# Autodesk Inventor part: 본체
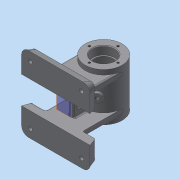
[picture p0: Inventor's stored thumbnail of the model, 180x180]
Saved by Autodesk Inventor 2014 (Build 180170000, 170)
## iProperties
Created: 2016-07
Part Number: 본체
Material: 일반
Document SubType Name: Modeling
Designer: 406-9
Density: 1 g/cm^3
Appearance: 기본값
Author: 406-9
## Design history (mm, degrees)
sketch "스케치1"
  geometry: L1 (-40, 55)-(40, 55); L2 (50, 45)-(50, -45); L3 (40, -55)-(-40, -55); L4 (-50, -45)-(-50, 45); L5 (-50, 55)-(50, -55); L6 (50, 55)-(-50, -55); A1 r 10 centre (-40, 45) between (-40, 55) and (-50, 45); A2 r 10 centre (40, 45) between (50, 45) and (40, 55); A3 r 10 centre (40, -45) between (40, -55) and (50, -45); A4 r 10 centre (-40, -45) between (-50, -45) and (-40, -55); 1 further point
  constraints: 12 end point, 8 point on circle, 8 point on line, 8 tangent, 4 centre point, 3 equal radius, 2 midpoint, 2 parallel, 1 horizontal, 1 perpendicular
  dimensions: "d0" = 100 distance of L5.end L6.end; "d1" = 110 distance of L6.end L5.start; "d119" = 10 radius of A1
sketch "스케치3"
  geometry: C1 r 27 at (0, 70); 1 further point
  constraints: 1 centre point, 1 vertical alignment
  dimensions: "d5" = 54 diameter of C1; "d6" = 70 distance of point (0, 0) C1.centre
extrude "돌출2" join sketch "스케치3" stored distance "d7" = 70; taper "d8" = 0 deg
node "작업 평면2"
sketch "스케치5"
  geometry: L1 (27, 35)-(-27, 35) reference; L2 (-27, -35)-(27, -35) reference; L3 (0, 35)-(0, -35); L4 (0, 35)-(-16, 35); L5 (-16, 35)-(-16, 23.3); L6 (-15.7, 23)-(-14, 23); L7 (-14, 23)-(-14, 21); L8 (-14, 21)-(-19, 21); L9 (-22, 18)-(-22, -18); L10 (-19, -21)-(-14, -21); L11 (-14, -21)-(-14, -23); L12 (-14, -23)-(-15.7, -23); L13 (-16, -23.3)-(-16, -35); L14 (0, -35)-(-16, -35); A1 r 3 centre (-19, -18) between (-22, -18) and (-19, -21); A2 r 3 centre (-19, 18) between (-19, 21) and (-22, 18); A3 r 0.3 centre (-15.7, -23.3) between (-15.7, -23) and (-16, -23.3); A4 r 0.3 centre (-15.7, 23.3) between (-16, 23.3) and (-15.7, 23); 5 further points
  constraints: 24 end point, 9 point on line, 8 point on circle, 8 tangent, 5 perpendicular, 4 centre point, 4 parallel, 2 collinear, 2 equal radius, 2 midpoint, 1 horizontal, 1 vertical
  dimensions: "d19" = 32 diameter of L5 L3; "d20" = 28 diameter of L7 L3; "d21" = 44 diameter of L9 L3; "d22" = 42 distance of point (-22, 21) point (-22, -21); "d23" = 12 distance of L4.end point (-16, 23); "d24" = 12 distance of point (-16, -23) L13.end; "d25" = 2 distance of L10.end L11.end; "d27" = 3 radius of A1; "d28" = 0.3 radius of A3
revolve "회전1" sketch "스케치5" stored, may be unused: angle "d26" = 90 deg
sketch "스케치6" dims "d29" = 42
  geometry: C1 r 16 at (0, 0) reference; 3 further points
  constraints: 2 vertical alignment, 1 coincident, 2 other
hole "구멍1" sketch "스케치6" at (0, 21) diameter "d30" = 3.242; stored, may be unused: countersink angle "d34" = 90 deg, drill point angle "d36" = 118 deg; dims "d31" = 8, "d32" = 4, "d33" = 2, "d35" = 10
sketch "스케치7"
  geometry: L1 (-27, 70)-(27, 70); L2 (0, 70)-(15.898, 44.559); L3 (0, 97)-(0, 43); L4 (15.898, 44.559)-(20.986, 47.738); L5 (20.986, 47.738)-(17.806, 52.826); L6 (17.806, 52.826)-(12.718, 49.647); A1 r 27 centre (0, 70) between (-27, 70) and (27, 70) reference; 1 further point
  constraints: 12 end point, 4 perpendicular, 4 point on circle, 2 midpoint, 1 coincident, 1 horizontal, 1 point on line
  dimensions: "d40" = 30 distance of L2.start L2.end; "d41" = 32 deg angle of L3 L2; "d42" = 12 diameter of L5 L2; "d43" = 6 distance of L4.end L5.end
node "작업 평면5"
sketch "스케치10"
  geometry: L1 (45, -20)-(22, -20); L2 (22, -20)-(22, 20); L3 (22, 20)-(45, 20); L4 (32, -8)-(32, 8); L5 (35.5, -8)-(35.5, 8); L6 (28.5, 8)-(28.5, -8); L7 (45, -20)-(45, 20); L8 (43, -35)-(43, 35) reference; A1 r 3.5 centre (32, -8) between (28.5, -8) and (35.5, -8); A2 r 3.5 centre (32, 8) between (35.5, 8) and (28.5, 8); 2 further points
  constraints: 16 end point, 4 point on circle, 4 tangent, 3 parallel, 2 centre point, 1 horizontal, 1 horizontal alignment, 1 midpoint, 1 perpendicular
  dimensions: "d62" = 32 distance of point (0, 0) point (32, 0); "d64" = 3.5 radius of A2; "d65" = 23 dimension on A2 A1; "d159" = 23 distance of L2.end L3.end; "d160" = 2 distance between parallel lines of L7 L8; "d161" = 20 distance from line of point (0, 0) L3; "d162" = 20 distance from line of L1 point (32, 0)
node "작업 평면3"
sketch "스케치11"
  geometry: C1 r 5 at (0, 0); 1 further point
  constraints: 1 centre point, 1 coincident
  dimensions: "d69" = 10 diameter of C1
extrude "돌출6" join sketch "스케치11" stored distance "d70" = 8; taper "d71" = 0 deg
hole "구멍3" diameter "d74" = 5.188; stored, may be unused: countersink angle "d78" = 90 deg, drill point angle "d80" = 118 deg; dims "d72" = 10, "d73" = 10, "d75" = 8, "d76" = 4, "d77" = 2, "d79" = 10
node "작업 평면4"
node "작업 평면6"
extrude "돌출7" join sketch "스케치1" distance "d120" = 12; taper "d121" = -20 deg
sketch "스케치17"
  geometry: L1 (27, -28)-(-27, -28); L2 (-27, -28)-(-27, 28); L3 (-27, 28)-(27, 28); L4 (27, 28)-(27, -28); L5 (27, -28)-(-27, 28); L6 (-27, -28)-(27, 28); L7 (-40, 55)-(40, 55) reference; 1 further point
  constraints: 12 end point, 2 midpoint, 2 parallel, 1 horizontal, 1 perpendicular
  dimensions: "d124" = 27 distance between parallel lines of L7 L3; "d125" = 54 distance of L1.start L1.end
extrude "돌출9" join sketch "스케치17" stored distance "d126" = 8; taper "d127" = 0 deg
sketch "스케치18"
  geometry: L1 (27, 12)-(27, 70) reference; L2 (-27, 12)-(27, 12) reference; L3 (-27, 12)-(-27, 70) reference; L4 (-45.632, 12)-(-40, 12) reference; L5 (-40, 0)-(-40, 12) reference; L6 (-50, 0)-(-40, 0) reference; L7 (-50, 0)-(-45.632, 12) reference; L8 (-40, 12)-(40, 12) reference; L9 (40, 0)-(40, 12) reference; L10 (-40, 0)-(40, 0) reference; L11 (-40, 0)-(-40, 12) reference; L12 (40, 12)-(45.632, 12) reference; L13 (50, 0)-(45.632, 12) reference; L14 (40, 0)-(50, 0) reference; L15 (40, 0)-(40, 12) reference; A1 r 27 centre (0, 70) between (-27, 70) and (27, 70) reference; 1 further point
extrude "돌출10" cut sketch "스케치18" stored distance "d128" = 40; taper "d129" = 0 deg
revolve "회전4" stored, may be unused: angle "d130" = 90 deg
hole "구멍6" diameter "d133" = 5.188; stored, may be unused: countersink angle "d137" = 90 deg, drill point angle "d139" = 118 deg; dims "d131" = 10, "d132" = 10, "d134" = 8, "d135" = 19.05, "d136" = 4.775, "d138" = 10
extrude "돌출8" join sketch "스케치10" stored distance "d122" = 8; taper "d123" = 0 deg
sketch "스케치19"
  geometry: 5 further points
  constraints: 2 horizontal alignment, 2 vertical alignment
  dimensions: "d140" = 75 distance of point (-37.5, 42.5) point (37.5, 42.5); "d141" = 85 distance of point (-37.5, 42.5) point (-37.5, -42.5); "d142" = 37.5 horizontal distance of point (-37.5, 42.5) point (0, 0); "d143" = 42.5 vertical distance of point (-37.5, 42.5) point (0, 0)
hole "구멍7" sketch "스케치19" at (-37.5, 42.5), (37.5, 42.5), (37.5, -42.5), (-37.5, -42.5) diameter "d144" = 6; stored, may be unused: countersink angle "d148" = 90 deg, drill point angle "d150" = 118 deg; dims "d145" = 8, "d146" = 10, "d147" = 4, "d149" = 10
fillet "모깎기1" dims "d151" = 2
chamfer "모따기1" distance "d152" = 1; stored, may be unused: second distance "d153" = 2, angle "d154" = 45 deg
node "작업 평면7"
sketch "스케치20"
  geometry: L1 (-27, -35)-(27, -35) reference; L2 (-27, -35)-(-27, 35) reference; 2 further points
  constraints: 1 other
  dimensions: "d155" = 35 distance from line of L1 point (0, 0); "d156" = 27 distance from line of L2 point (0, 0)
feature "엠보싱1" sketch "스케치20" dims "d0" = 100, "d1" = 110, "d19" = 32, "d20" = 28, "d21" = 44, "d22" = 42, "d23" = 12, "d24" = 12, "d25" = 2, "d27" = 3, "d28" = 0.3, "d119" = 10, "d157" = 0.5, "d158" = 0
node "솔리드1"
pattern_circular "원형 패턴1" dims angle "d38" = 360 deg
mirror "대칭1"
node "투영된 루프2"
node "투영된 루프3"
node "투영된 루프4"
node "투영된 루프5"
other parameters: "d103" = 12
